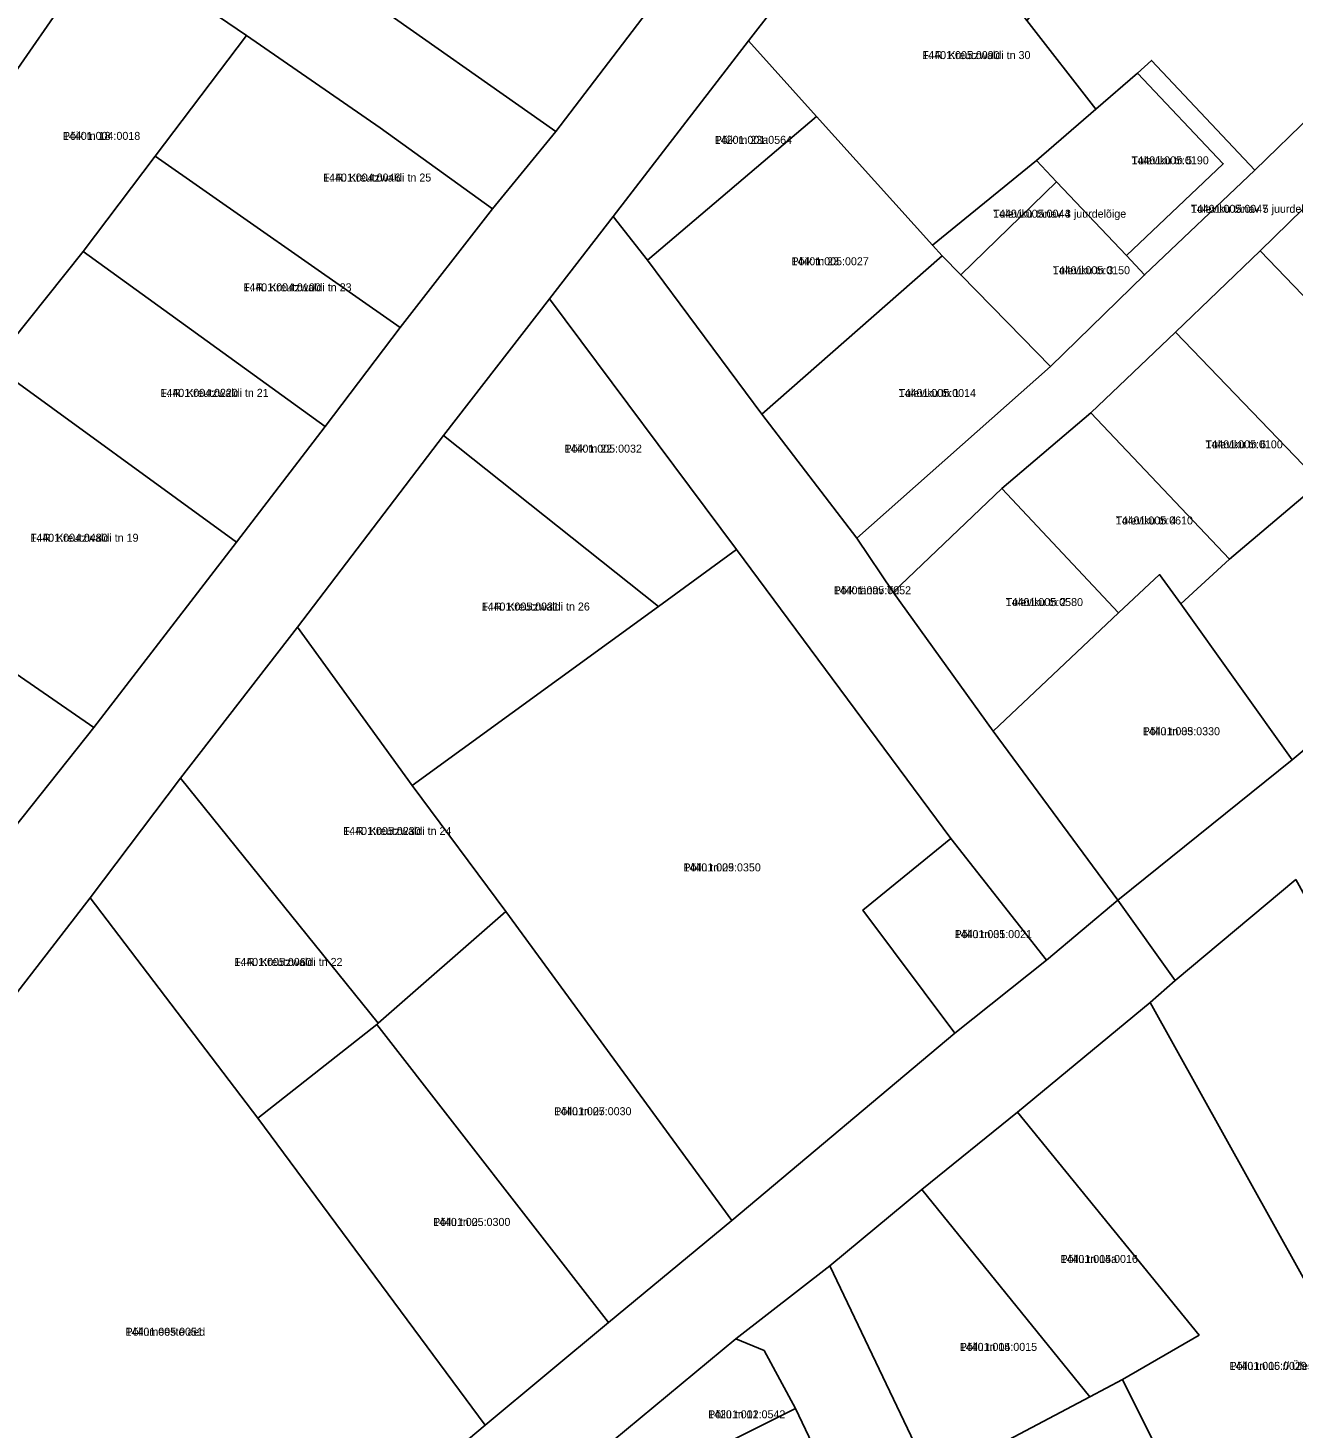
# Model space of a CAD drawing. Extents: x 640657 to 665127, y 6395726 to 6426831.
# Drawn here: x 650572.3 to 650809.6, y 6412630.2 to 6412892.7 of the extents above; entities that cross this region are included whole.
import ezdxf

# ---------------------------------------------------------------- set-up
doc = ezdxf.new("R2010")
doc.units = 0
for name, color, linetype in [('L_AADRESS', 7, 'Continuous'), ('PIIR', 7, 'Continuous'), ('TUNNUS', 7, 'Continuous')]:
    doc.layers.add(name, color=color, linetype=linetype)

msp = doc.modelspace()

# ---------------------------------------------------------------- linework, layer by layer
at = {"layer": 'PIIR'}
for points in [[(650401.68, 6412620.02), (650443.31, 6412635.66), (650502.99, 6412658.87), (650531.76, 6412695.05), (650559.55, 6412729.99), (650584.65, 6412761.55), (650611.45, 6412796.26), (650628.07, 6412817.98), (650642.14, 6412836.53), (650659.43, 6412858.77), (650671.35, 6412873.26), (650691.08, 6412899.24), (650704.96, 6412917.1), (650717.93, 6412933.8), (650741.65, 6412963.62), (650765.03, 6412993.85), (650786.55, 6413021.63), (650809.09, 6413051.96), (650817.6, 6413061.15)], [(650817.7, 6413031.91), (650806.76, 6413017.69), (650784.43, 6412989.36), (650760.68, 6412958.63), (650735.21, 6412925.98), (650707.5, 6412890.28), (650682.06, 6412857.34), (650670.16, 6412841.93), (650650.26, 6412816.25), (650622.9, 6412780.36), (650600.95, 6412752.04), (650584, 6412729.6), (650523.13, 6412650.87), (650462.26, 6412625.96)], [(650556.73, 6412953.59), (650575.99, 6412939.48), (650600.47, 6412922.38), (650604.01, 6412919.95), (650612.9, 6412914.8), (650634.13, 6412899.46), (650671.35, 6412873.26), (650659.43, 6412858.77), (650638.35, 6412874), (650613.3, 6412891.26), (650587.03, 6412909.19), (650547.67, 6412936.14)], [(650810.12, 6412733.02), (650787.5, 6412714.1), (650776.77, 6412729.16), (650809.43, 6412755.49), (650841.85, 6412782.53)], [(650574.96, 6412560.92), (650658.1, 6412630.7), (650681.21, 6412649.94), (650704.32, 6412669.08), (650746.17, 6412704.22), (650763.35, 6412717.91), (650776.77, 6412729.16), (650787.5, 6412714.1), (650782.82, 6412709.96), (650757.9, 6412689.4), (650740, 6412674.9), (650722.7, 6412660.6), (650705.1, 6412646.9), (650679.43, 6412625.62)], [(650731.8, 6412601.29), (650716.31, 6412633.84), (650710.4, 6412644.7), (650705.1, 6412646.9), (650722.7, 6412660.6), (650741.9, 6412620.4)]]:
    msp.add_lwpolyline(points, dxfattribs=at)
for points in [[(650727.79, 6412797.05), (650764.12, 6412829.22), (650781.76, 6412846.39), (650802.47, 6412866.04), (650824.08, 6412887.05), (650843.09, 6412905.57), (650862, 6412923.4), (650879, 6412940), (650896.59, 6412956.91), (650903.31, 6412947.28), (650883.38, 6412927.9), (650866.67, 6412911.86), (650850.73, 6412896.72), (650834.83, 6412881.39), (650819.43, 6412866.53), (650803.47, 6412850.91), (650787.59, 6412835.68), (650771.66, 6412820.55), (650754.96, 6412806.32), (650734.58, 6412786.93)], [(650587.03, 6412909.19), (650570.41, 6412885.11), (650528.27, 6412908.65), (650547.67, 6412936.14)], [(650653.47, 6412925.91), (650691.08, 6412899.24), (650671.35, 6412873.26), (650634.13, 6412899.46)], [(650735.21, 6412925.98), (650759.7, 6412894.12), (650772.63, 6412877.46), (650761.52, 6412867.85), (650741.97, 6412851.94), (650720.2, 6412876.12), (650707.5, 6412890.28)], [(650759.7, 6412894.12), (650786.31, 6412924.61), (650824.08, 6412887.05), (650802.47, 6412866.04), (650783.09, 6412886.6), (650780.41, 6412884.25), (650772.63, 6412877.46)], [(650587.03, 6412909.19), (650613.3, 6412891.26), (650596.19, 6412868.66), (650582.65, 6412850.8), (650565.69, 6412829.54), (650562.63, 6412831.16), (650544.44, 6412845.81), (650570.41, 6412885.11)], [(650613.3, 6412891.26), (650638.35, 6412874), (650659.43, 6412858.77), (650642.14, 6412836.53), (650596.19, 6412868.66)], [(650720.2, 6412876.12), (650688.52, 6412849.18), (650682.06, 6412857.34), (650707.5, 6412890.28)], [(650780.41, 6412884.25), (650783.09, 6412886.6), (650802.47, 6412866.04), (650781.76, 6412846.39), (650778.4, 6412850.02), (650796.51, 6412867.23)], [(650761.52, 6412867.85), (650772.63, 6412877.46), (650780.41, 6412884.25), (650796.51, 6412867.23), (650778.4, 6412850.02), (650765.26, 6412863.82)], [(650709.94, 6412820.28), (650688.52, 6412849.18), (650720.2, 6412876.12), (650741.97, 6412851.94), (650743.81, 6412849.94)], [(650596.19, 6412868.66), (650642.14, 6412836.53), (650628.07, 6412817.98), (650582.65, 6412850.8)], [(650741.97, 6412851.94), (650761.52, 6412867.85), (650765.26, 6412863.82), (650747.27, 6412846.38), (650743.81, 6412849.94)], [(650803.47, 6412850.91), (650819.43, 6412866.53), (650848.73, 6412835.25), (650831.89, 6412821.36)], [(650747.27, 6412846.38), (650765.26, 6412863.82), (650778.4, 6412850.02), (650781.76, 6412846.39), (650764.12, 6412829.22), (650758.86, 6412834.58)], [(650682.06, 6412857.34), (650688.52, 6412849.18), (650709.94, 6412820.28), (650727.79, 6412797.05), (650734.58, 6412786.93), (650753.38, 6412760.87), (650776.77, 6412729.16), (650763.35, 6412717.91), (650745.42, 6412740.74), (650705.23, 6412794.91), (650670.16, 6412841.93)], [(650582.65, 6412850.8), (650628.07, 6412817.98), (650611.45, 6412796.26), (650565.69, 6412829.54)], [(650727.79, 6412797.05), (650709.94, 6412820.28), (650743.81, 6412849.94), (650747.27, 6412846.38), (650758.86, 6412834.58), (650764.12, 6412829.22)], [(650787.59, 6412835.68), (650803.47, 6412850.91), (650831.89, 6412821.36), (650820.3, 6412811.59), (650814.7, 6412807.49)], [(650650.26, 6412816.25), (650670.16, 6412841.93), (650705.23, 6412794.91), (650690.6, 6412784.22)], [(650797.72, 6412793.12), (650771.66, 6412820.55), (650787.59, 6412835.68), (650814.7, 6412807.49)], [(650534.02, 6412796.48), (650562.63, 6412831.16), (650565.69, 6412829.54), (650611.45, 6412796.26), (650584.65, 6412761.55)], [(650771.66, 6412820.55), (650797.72, 6412793.12), (650788.56, 6412784.71), (650784.57, 6412790.2), (650776.85, 6412783.03), (650754.96, 6412806.32)], [(650650.26, 6412816.25), (650690.6, 6412784.22), (650644.37, 6412750.68), (650622.9, 6412780.36)], [(650820.3, 6412811.59), (650841.85, 6412782.53), (650809.43, 6412755.49), (650788.56, 6412784.71), (650797.72, 6412793.12), (650814.7, 6412807.49)], [(650734.58, 6412786.93), (650754.96, 6412806.32), (650776.85, 6412783.03), (650753.38, 6412760.87)], [(650559.55, 6412729.99), (650515.2, 6412759.31), (650503.6, 6412766.24), (650526.12, 6412801.71), (650534.02, 6412796.48), (650584.65, 6412761.55)], [(650704.32, 6412669.08), (650661.95, 6412727.04), (650644.37, 6412750.68), (650690.6, 6412784.22), (650705.23, 6412794.91), (650745.42, 6412740.74), (650728.93, 6412727.28), (650746.17, 6412704.22)], [(650776.77, 6412729.16), (650753.38, 6412760.87), (650776.85, 6412783.03), (650784.57, 6412790.2), (650788.56, 6412784.71), (650809.43, 6412755.49)], [(650622.9, 6412780.36), (650644.36, 6412750.66), (650661.95, 6412727.04), (650638.03, 6412706.08), (650600.95, 6412752.04)], [(650600.95, 6412752.04), (650638.03, 6412706.08), (650637.73, 6412705.82), (650615.4, 6412688.3), (650584, 6412729.6)], [(650745.42, 6412740.74), (650763.35, 6412717.91), (650746.17, 6412704.22), (650728.93, 6412727.28)], [(650810.12, 6412733.02), (650833.84, 6412690.24), (650865.67, 6412631.46), (650834.03, 6412617.93), (650782.82, 6412709.96), (650787.5, 6412714.1)], [(650523.13, 6412650.87), (650584, 6412729.6), (650615.4, 6412688.3), (650658.1, 6412630.7), (650574.96, 6412560.92), (650573.52, 6412570.41), (650550.64, 6412602.33)], [(650704.32, 6412669.08), (650681.21, 6412649.94), (650637.73, 6412705.82), (650638.03, 6412706.08), (650661.95, 6412727.04)], [(650782.82, 6412709.96), (650834.03, 6412617.93), (650837.5, 6412611.3), (650799.06, 6412596.2), (650777.6, 6412639.3), (650792, 6412647.6), (650757.9, 6412689.4)], [(650681.21, 6412649.94), (650658.1, 6412630.7), (650615.4, 6412688.3), (650637.73, 6412705.82)], [(650740, 6412674.9), (650757.9, 6412689.4), (650792, 6412647.6), (650777.6, 6412639.3), (650771.5, 6412636)], [(650740, 6412674.9), (650771.5, 6412636), (650741.9, 6412620.4), (650722.7, 6412660.6)], [(650716.31, 6412633.84), (650682.84, 6412617.1), (650679.43, 6412625.62), (650705.1, 6412646.9), (650710.4, 6412644.7)], [(650777.6, 6412639.3), (650799.06, 6412596.2), (650761.2, 6412581.11), (650741.9, 6412620.4), (650771.5, 6412636)], [(650682.84, 6412617.1), (650716.31, 6412633.84), (650731.8, 6412601.29), (650695.95, 6412584.31)]]:
    msp.add_lwpolyline(points, close=True, dxfattribs=at)

# ---------------------------------------------------------------- texts
at = {"layer": 'L_AADRESS'}
for s, p in [('F. R. Kreutzwaldi tn 30', (650740.07, 6412886.86)), ('Põik tn 18', (650578.87, 6412871.71)), ('Põik tn 23a', (650701.13, 6412870.97)), ('Tuleviku tn 5', (650779.3, 6412867.13)), ('F. R. Kreutzwaldi tn 25', (650627.67, 6412863.9)), ('Tuleviku tänav 5 juurdelõige', (650790.43, 6412858.04)), ('Tuleviku tänav 3 juurdelõige', (650753.34, 6412857.12)), ('Põik tn 23', (650715.53, 6412848.2)), ('Tuleviku tn 3', (650764.53, 6412846.52)), ('F. R. Kreutzwaldi tn 23', (650612.72, 6412843.32)), ('F. R. Kreutzwaldi tn 21', (650597.17, 6412823.53)), ('Tuleviku tn 1', (650735.63, 6412823.5)), ('Tuleviku tn 6', (650793.18, 6412813.88)), ('Põik tn 22', (650672.97, 6412813.07)), ('Tuleviku tn 4', (650776.34, 6412799.6)), ('F. R. Kreutzwaldi tn 19', (650572.76, 6412796.36)), ('Põik tänav T2', (650723.46, 6412786.51)), ('F. R. Kreutzwaldi tn 26', (650657.41, 6412783.46)), ('Tuleviku tn 2', (650755.71, 6412784.3)), ('Põllu tn 33', (650781.41, 6412760.08)), ('F. R. Kreutzwaldi tn 24', (650631.45, 6412741.38)), ('Põllu tn 29', (650695.27, 6412734.55)), ('Põllu tn 31', (650746.14, 6412722.04)), ('F. R. Kreutzwaldi tn 22', (650611.02, 6412716.82)), ('Põllu tn 27', (650671.02, 6412688.83)), ('Põllu tn 25', (650648.3, 6412668.07)), ('Põllu tn 14a', (650766, 6412661.13)), ('Põllumeeste aed', (650590.62, 6412647.48)), ('Põllu tn 14', (650747.1, 6412644.64)), ('Põllu tn 16 // Ülesõidu tn 3a', (650797.7, 6412641.08)), ('Põllu tn 12', (650699.88, 6412632))]:
    msp.add_text(s, height=1.5, dxfattribs=at).set_placement(p)
at = {"layer": 'TUNNUS'}
for s, p in [('14401:005:0090', (650740.07, 6412886.86)), ('14401:004:0018', (650578.87, 6412871.71)), ('14201:001:0564', (650701.13, 6412870.97)), ('14401:005:0190', (650779.3, 6412867.13)), ('14401:004:0046', (650627.67, 6412863.9)), ('14401:005:0047', (650790.43, 6412858.04)), ('14401:005:0044', (650753.34, 6412857.12)), ('14401:005:0027', (650715.53, 6412848.2)), ('14401:005:0150', (650764.53, 6412846.52)), ('14401:004:0100', (650612.72, 6412843.32)), ('14401:004:0220', (650597.17, 6412823.53)), ('14401:005:0014', (650735.63, 6412823.5)), ('14401:005:0100', (650793.18, 6412813.88)), ('14401:005:0032', (650672.97, 6412813.07)), ('14401:005:0610', (650776.34, 6412799.6)), ('14401:004:0480', (650572.76, 6412796.36)), ('14401:005:0052', (650723.46, 6412786.51)), ('14401:005:0031', (650657.41, 6412783.46)), ('14401:005:0580', (650755.71, 6412784.3)), ('14401:005:0330', (650781.41, 6412760.08)), ('14401:005:0230', (650631.45, 6412741.38)), ('14401:005:0350', (650695.27, 6412734.55)), ('14401:005:0021', (650746.14, 6412722.04)), ('14401:005:0060', (650611.02, 6412716.82)), ('14401:005:0030', (650671.02, 6412688.83)), ('14401:005:0300', (650648.3, 6412668.07)), ('14401:005:0016', (650766, 6412661.13)), ('14401:005:0051', (650590.62, 6412647.48)), ('14401:005:0015', (650747.1, 6412644.64)), ('14401:005:0029', (650797.7, 6412641.08)), ('14201:001:0542', (650699.88, 6412632))]:
    msp.add_text(s, height=1.5, dxfattribs=at).set_placement(p)

doc.saveas('drawing.dxf')
